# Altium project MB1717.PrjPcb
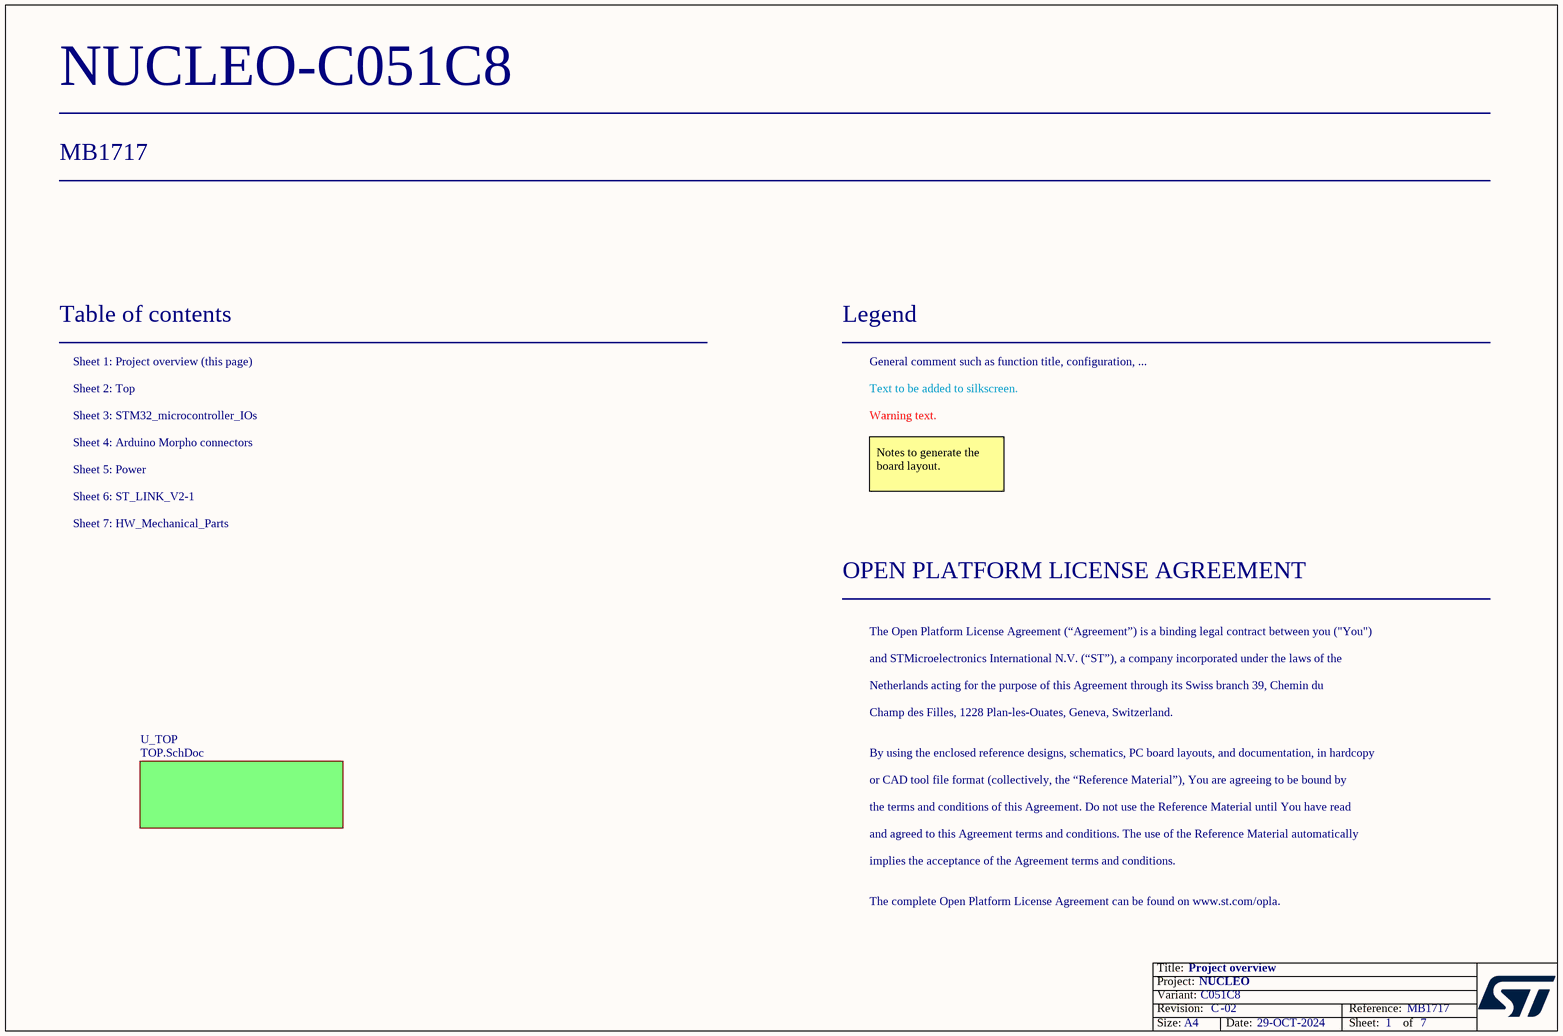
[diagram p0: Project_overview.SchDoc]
VariantName: C051C8; Board_Reference: MB1717; Board_PCB_Revision: C; Board_Name: NUCLEO; Board_Document_Date: 29-OCT-2024; Board_Assembly_Revision: 02
7 sheets, 148 parts. Net scope: flat (ports and power ports of the same name join across sheets).
Board file: MB1717.PcbDoc
Sheets:
  Project_overview.SchDoc
    U_TOP = TOP.SchDoc
      ST_LINK_V2-1 = ST_LINK_V2-1.SchDoc
      MCU = STM32_microcontroller_IOs.SchDoc
      Power = Power.SchDoc
      HW_Mechanical_Parts = HW_Mechanical_Parts.SchDoc
      U_Arduino_Morpho_connectors = Arduino_Morpho_connectors.SchDoc

## Sheet Project_overview.SchDoc: Project overview
size A4; Date: Not used; ApprovedBy: Not used; CheckedBy: Not used; Author: Not used; CompanyName: STMicroelectronics; DrawnBy: Not used; Engineer: Not used; Organization: Not used; Address1: Not used; Address2: Not used; Address3: Not used; Address4: Not used; DocumentNumber: 1; Revision: Not used; SheetNumber: 1; SheetTotal: 7

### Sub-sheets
U_TOP = TOP.SchDoc: no entries

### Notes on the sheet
- Table of contents
- Sheet 1: Project overview (this page)
- Legend
- General comment such as function title, configuration, ...
- Sheet 2: Top
- Sheet 4: Arduino Morpho connectors
- Sheet 3: STM32_microcontroller_IOs
- Text to be added to silkscreen.
- Warning text.
- Sheet 5: Power
- Sheet 6: ST_LINK_V2-1
- Notes to generate the board layout.
- Sheet 7: HW_Mechanical_Parts
- OPEN PLATFORM LICENSE AGREEMENT
- The Open Platform License Agreement (“Agreement”) is a binding legal contract between you ("You")
- and STMicroelectronics International N.V. (“ST”), a company incorporated under the laws of the
- Netherlands acting for the purpose of this Agreement through its Swiss branch 39, Chemin du
- Champ des Filles, 1228 Plan-les-Ouates, Geneva, Switzerland.
- By using the enclosed reference designs, schematics, PC board layouts, and documentation, in hardcopy
- or CAD tool file format (collectively, the “Reference Material”), You are agreeing to be bound by
- the terms and conditions of this Agreement. Do not use the Reference Material until You have read
- and agreed to this Agreement terms and conditions. The use of the Reference Material automatically
- implies the acceptance of the Agreement terms and conditions.
- The complete Open Platform License Agreement can be found on www.st.com/opla.

## Sheet TOP.SchDoc: TOP
size A4; CompanyName: STMicroelectronics; Organization: Microcontrollers Division; SheetNumber: 2; SheetTotal: 7
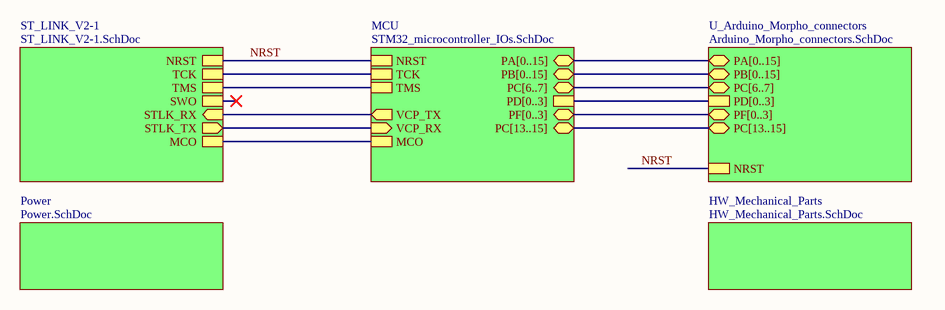
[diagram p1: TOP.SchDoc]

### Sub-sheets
HW_Mechanical_Parts = HW_Mechanical_Parts.SchDoc: no entries
MCU = STM32_microcontroller_IOs.SchDoc: NRST, MCO, PA[0..15] (bidir), PB[0..15] (bidir), TCK, TMS, PD[0..3], PC[6..7] (bidir), PC[13..15] (bidir), VCP_RX (in), VCP_TX (out), PF[0..3] (bidir)
Power = Power.SchDoc: no entries
ST_LINK_V2-1 = ST_LINK_V2-1.SchDoc: TMS, TCK, MCO, NRST, STLK_RX (in), STLK_TX (out), SWO
U_Arduino_Morpho_connectors = Arduino_Morpho_connectors.SchDoc: PA[0..15] (bidir), PB[0..15] (bidir), NRST, PD[0..3], PC[6..7] (bidir), PC[13..15] (bidir), PF[0..3] (bidir)

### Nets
NRST: sheet ST_LINK_V2-1/NRST, sheet MCU/NRST, sheet U_Arduino_Morpho_connectors/NRST
(unnamed): sheet ST_LINK_V2-1/TMS, sheet MCU/TMS
(unnamed): sheet ST_LINK_V2-1/TCK, sheet MCU/TCK  [a separate net that carries the same name]
(unnamed): sheet ST_LINK_V2-1/MCO, sheet MCU/MCO  [a separate net that carries the same name]
(unnamed): sheet ST_LINK_V2-1/STLK_RX, sheet MCU/VCP_TX  [a separate net that carries the same name]
(unnamed): sheet ST_LINK_V2-1/STLK_TX, sheet MCU/VCP_RX  [a separate net that carries the same name]

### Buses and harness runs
bus sheet MCU/PA[0..15] = sheet U_Arduino_Morpho_connectors/PA[0..15]
bus sheet MCU/PB[0..15] = sheet U_Arduino_Morpho_connectors/PB[0..15]
bus sheet MCU/PC[6..7] = sheet U_Arduino_Morpho_connectors/PC[6..7]
bus sheet MCU/PC[13..15] = sheet U_Arduino_Morpho_connectors/PC[13..15]
bus sheet MCU/PD[0..3] = sheet U_Arduino_Morpho_connectors/PD[0..3]
bus sheet MCU/PF[0..3] = sheet U_Arduino_Morpho_connectors/PF[0..3]

## Sheet ST_LINK_V2-1.SchDoc: ST_LINK_V2-1
size A4; CompanyName: STMicroelectronics; Organization: Microcontrollers Division; SheetNumber: 6; SheetTotal: 7
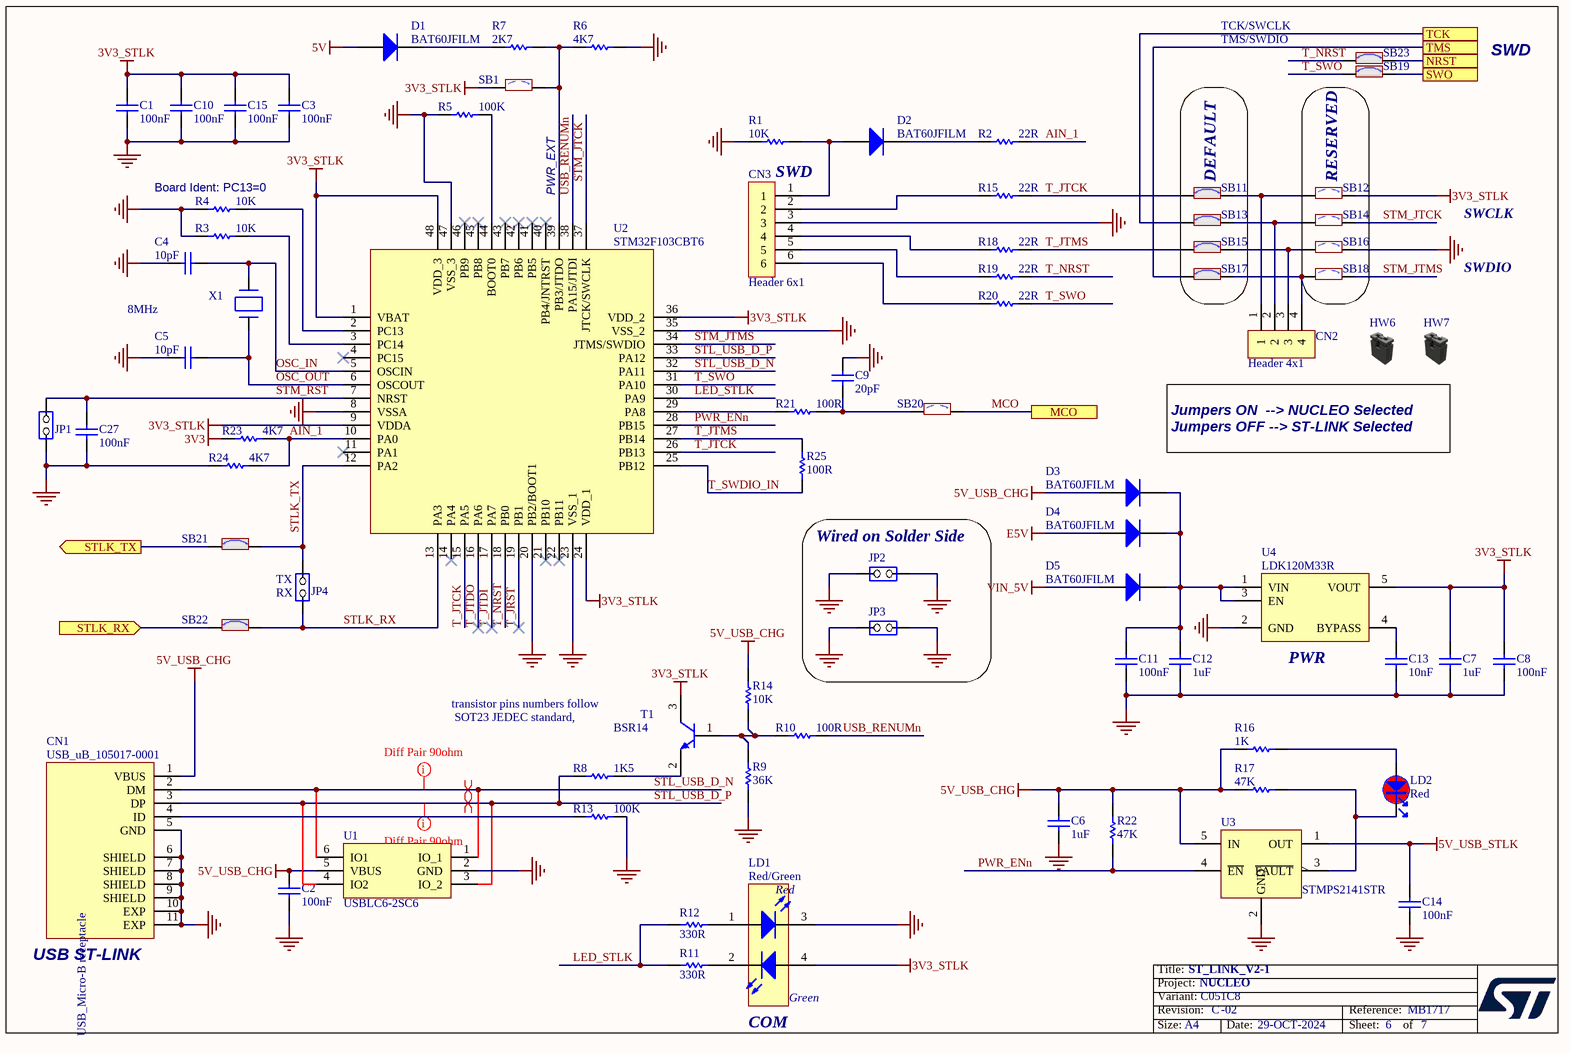
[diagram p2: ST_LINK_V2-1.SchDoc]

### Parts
C1  value 100nF  [C0603]  (hidden comment: Capacitor)
C2  value 100nF  [C0603]  (hidden comment: Capacitor)
C3  value 100nF  [C0603]  (hidden comment: Capacitor)
C4  value 10pF  [C0603]  (hidden comment: Capacitor)
C5  value 10pF  [C0603]  (hidden comment: Capacitor)
C6  value 1uF  [C0603]  (hidden comment: Capacitor)
C7  value 1uF  [C0603]  (hidden comment: Capacitor)
C8  value 100nF  [C0603]  (hidden comment: Capacitor)
C9  value 20pF  [C0603]  (hidden comment: Capacitor)
C10  value 100nF  [C0603]  (hidden comment: Capacitor)
C11  value 100nF  [C0603]  (hidden comment: Capacitor)
C12  value 1uF  [C0603]  (hidden comment: Capacitor)
C13  value 10nF  [C0603]  (hidden comment: Capacitor)
C14  value 100nF  [C0603]  (hidden comment: Capacitor)
C15  value 100nF  [C0603]  (hidden comment: Capacitor)
C27  value 100nF  [C0603]  (hidden comment: Capacitor)
CN1  value USB_uB_105017-0001  [CON_USBMICROB_MOLEX_105017-0001_H2P90]  (hidden comment: USB_uB_105017.0001)
CN2  Header 4x1  [CON_SAMTEC_TSW-104-07-G-S]
CN3  Header 6x1  [CON_SAMTEC_TSW-106-07-X-S]
D1  BAT60JFILM  [DIO_SOD323]
D2  BAT60JFILM  [DIO_SOD323]
D3  BAT60JFILM  [DIO_SOD323]
D4  BAT60JFILM  [DIO_SOD323]
D5  BAT60JFILM  [DIO_SOD323]
HW6  Shunt Black 2.54mm  (value not drawn)  (mechanical)
HW7  Shunt Black 2.54mm  (value not drawn)  (mechanical)
JP1  Jumper_Header 2x1  [CON_SAMTEC_TSW-102-07-G-S]  (value not drawn)
JP2  Jumper_Header 2x1  [CON_SAMTEC_TSW-102-09-X-S]  (value not drawn)
JP3  Jumper_Header 2x1  [CON_SAMTEC_TSW-102-09-X-S]  (value not drawn)
JP4  Jumper_Header 2x1  [CON_SAMTEC_TSW-102-07-G-S]  (value not drawn)
LD1  value Red/Green  [LED_BI-GR_WE-150141SV73110]  (hidden comment: LED_BICOLOR)
LD2  value Red  [LED_0603_OSRAM_LS-Q976-NR-1_RED_1A2K_H0P8]  (hidden comment: LED_red)
R1  value 10K  [R0603]  (hidden comment: Resistor)
R2  value 22R  [R0603]  (hidden comment: Resistor)
R3  value 10K  [R0603]  (hidden comment: Resistor)
R4  value 10K  [R0603]  (hidden comment: Resistor)
R5  value 100K  [R0603]  (hidden comment: Resistor)
R6  value 4K7  [R0603]  (hidden comment: Resistor)
R7  value 2K7  [R0603]  (hidden comment: Resistor)
R8  value 1K5  [R0603]  (hidden comment: Resistor)
R9  value 36K  [R0603]  (hidden comment: Resistor)
R10  value 100R  [R0603]  (hidden comment: Resistor)
R11  value 330R  [R0603]  (hidden comment: Resistor)
R12  value 330R  [R0603]  (hidden comment: Resistor)
R13  value 100K  [R0603]  (hidden comment: Resistor)
R14  value 10K  [R0603]  (hidden comment: Resistor)
R15  value 22R  [R0603]  (hidden comment: Resistor)
R16  value 1K  [R0603]  (hidden comment: Resistor)
R17  value 47K  [R0603]  (hidden comment: Resistor)
R18  value 22R  [R0603]  (hidden comment: Resistor)
R19  value 22R  [R0603]  (hidden comment: Resistor)
R20  value 22R  [R0603]  (hidden comment: Resistor)
R21  value 100R  [R0603]  (hidden comment: Resistor)
R22  value 47K  [R0603]  (hidden comment: Resistor)
R23  value 4K7  [R0603]  (hidden comment: Resistor)
R24  value 4K7  [R0603]  (hidden comment: Resistor)
R25  value 100R  [R0603]  (hidden comment: Resistor)
SB1  SB_OFF  [SOLDER-BRIDGE_R0603-0R]  (value not drawn)
SB11  SB_ON  [SOLDER-BRIDGE_R0603-0R]  (value not drawn)
SB12  SB_OFF  [SOLDER-BRIDGE_R0603-0R]  (value not drawn)
SB13  SB_ON  [SOLDER-BRIDGE_R0603-0R]  (value not drawn)
SB14  SB_OFF  [SOLDER-BRIDGE_R0603-0R]  (value not drawn)
SB15  SB_ON  [SOLDER-BRIDGE_R0603-0R]  (value not drawn)
SB16  SB_OFF  [SOLDER-BRIDGE_R0603-0R]  (value not drawn)
SB17  SB_ON  [SOLDER-BRIDGE_R0603-0R]  (value not drawn)
SB18  SB_OFF  [SOLDER-BRIDGE_R0603-0R]  (value not drawn)
SB19  SB_ON  [SOLDER-BRIDGE_R0603-0R]  (value not drawn)
SB20  SB_OFF  [SOLDER-BRIDGE_R0603-0R]  (value not drawn)
SB21  SB_ON  [SOLDER-BRIDGE_R0603-0R]  (value not drawn)
SB22  SB_ON  [SOLDER-BRIDGE_R0603-0R]  (value not drawn)
SB23  SB_ON  [SOLDER-BRIDGE_R0603-0R]  (value not drawn)
T1  value BSR14  [NPN_SOT23]  (hidden comment: 9013-SOT23)
U1  USBLC6-2SC6  [ESD_SOT23-6L]
U2  STM32F103CBT6  [ICC_LQFP48_7X7_P050]
U3  STMPS2141STR  [MOS_SOT23-5L]
U4  LDK120M33R  [REG_SOT23-5L]
X1  value 8MHz  [CRY_NX3225GD_2P]  (hidden comment: XTAL_2_PINS)

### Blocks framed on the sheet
DEFAULT: SB11 SB13 SB15 SB17
RESERVED: SB12 SB14 SB16 SB18
Wired on Solder Side: JP2 JP3

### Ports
MCO, NRST, STLK_RX (in), STLK_TX (out), SWO, TCK, TMS

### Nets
3V3: R23.1
3V3_STLK: C1.2 C3.2 C7.2 C8.2 C10.2 C15.2 LD1.4(Green_anode) SB1.1 SB12.2 T1.3(C) U2.1(VBAT) U2.9(VDDA) U2.24(VDD_1) U2.36(VDD_2) U2.48(VDD_3) U4.5(VOUT)
5V: D1.1(A)
5V_USB_CHG: C2.2 C6.2 CN1.1(VBUS) D3.1(A) R14.2 R16.2 R17.2 R22.2 U1.5(VBUS) U3.5(IN)
5V_USB_STLK: C14.2 U3.1(OUT)
E5V: D4.1(A)
GND: C1.1 C2.1 C3.1 C4.1 C5.1 C6.1 C7.1 C8.1 C9.2 C10.1 C11.1 C12.1 C13.1 C14.1 C15.1 C27.2 CN1.5(GND) CN1.6(SHIELD) CN1.7(SHIELD) CN1.8(SHIELD) CN1.9(SHIELD) CN1.10(EXP) CN1.11(EXP) CN3.3 JP1.2(NO) JP2.1(COMMON) JP2.2(NO) JP3.1(COMMON) JP3.2(NO) LD1.3(RED_cathode) R1.2 R3.1 R4.1 R5.1 R6.2 R9.1 R13.2 R24.1 SB16.2 U1.2(GND) U2.8(VSSA) U2.20(PB2/BOOT1) U2.23(VSS_1) U2.35(VSS_2) U2.47(VSS_3) U3.2(GND) U4.2(GND)
VIN_5V: D5.1(A)
AIN_1: R2.2 R23.2 R24.2 U2.10(PA0)
LED_STLK: R11.1 R12.1 U2.30(PA9)
MCO: SB20.2 ; port MCO
NRST: SB23.2 ; port NRST
OSC_IN: C4.2 U2.5(OSCIN) X1.2(X2)
OSC_OUT: C5.2 U2.6(OSCOUT) X1.1(X1)
PA13: SB17.1 ; port TMS
PA14: SB13.1 ; port TCK
PWR_ENn: R22.1 U2.28(PB15) U3.4(~{EN})
STL_USB_D_N: CN1.2(DM) U1.1(IO_1) U1.6(IO1) U2.32(PA11)
STL_USB_D_P: CN1.3(DP) R8.1 U1.3(IO_2) U1.4(IO2) U2.33(PA12)
STLK_RX: JP4.1(COMMON) SB22.2 U2.13(PA3)
STLK_TX: JP4.2(NO) SB21.2 U2.12(PA2)
STM_JTCK: SB14.2 U2.37(JTCK/SWCLK)
STM_JTMS: SB18.2 U2.34(JTMS/SWDIO)
STM_RST: C27.1 JP1.1(COMMON) U2.7(NRST)
T_JRST: U2.19(PB1)
T_JTCK: R15.2 SB11.1 U2.15(PA5) U2.26(PB13)
T_JTDI: U2.17(PA7)
T_JTDO: U2.16(PA6)
T_JTMS: R18.2 R25.2 SB15.1 U2.27(PB14)
T_NRST: R19.2 SB23.1 U2.18(PB0)
T_SWDIO_IN: R25.1 U2.25(PB12)
T_SWO: R20.2 SB19.1 U2.31(PA10)
USB_RENUMn: R10.2 U2.38(PA15/JTDI)
NetC9_1: C9.1 R21.2 SB20.1
NetC11_2: C11.2 C12.2 D3.2(K) D4.2(K) D5.2(K) U4.1(VIN) U4.3(EN)
NetC13_2: C13.2 U4.4(BYPASS)
NetCN1_4: CN1.4(ID) R13.1
NetCN2_1: CN2.1 SB11.2 SB12.1
NetCN2_2: CN2.2 SB13.2 SB14.1
NetCN2_3: CN2.3 SB15.2 SB16.1
NetCN2_4: CN2.4 SB17.2 SB18.1
NetCN3_1: CN3.1 D2.1(A) R1.1
NetCN3_2: CN3.2 R15.1
NetCN3_4: CN3.4 R18.1
NetCN3_5: CN3.5 R19.1
NetCN3_6: CN3.6 R20.1
NetD1_2: D1.2(K) R7.1
NetD2_2: D2.2(K) R2.1
NetLD1_1: LD1.1(Red_anode) R12.2
NetLD1_2: LD1.2(Green_cathode) R11.2
NetLD2_1: LD2.1 R16.1
NetLD2_2: LD2.2 R17.1 U3.3(~{FAULT})
NetR3_2: R3.2 U2.3(PC14)
NetR4_2: R4.2 U2.2(PC13)
NetR5_2: R5.2 U2.44(BOOT0)
NetR6_1: R6.1 R7.2 SB1.2 U2.39(PB3/JTDO)
NetR8_2: R8.2 T1.2(E)
NetR9_2: R9.2 R10.1 R14.1 T1.1(B)
NetR21_1: R21.1 U2.29(PA8)
NetSB19_2: SB19.2 ; port SWO
NetSB21_1: SB21.1 ; port STLK_TX
NetSB22_1: SB22.1 ; port STLK_RX

Not connected (* = marked no-connect by the designer): U2 4(PC15)* 11(PA1)* 14(PA4)* 21(PB10)* 22(PB11)* 40(PB4/JNTRST)* 41(PB5)* 42(PB6)* 43(PB7)* 45(PB8)* 46(PB9)*

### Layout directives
mark named Diff Pair 90ohm: STL_USB_D_N, STL_USB_D_P
differential pair: STL_USB_D_N, STL_USB_D_P

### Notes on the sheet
- TCK/SWCLK
- TMS/SWDIO
- SWD
- (near R4) Board Ident: PC13=0
- PWR_EXT
- SWCLK
- SWDIO
- Jumpers ON  --> NUCLEO Selected
  Jumpers OFF --> ST-LINK Selected
- (near JP4) TX
- (near JP4) RX
- (near U4) PWR
- (near T1) transistor pins numbers follow
  SOT23 JEDEC standard,
- (near CN1) USB ST-LINK
- COM

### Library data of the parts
C1-C3 C8 C10 C11 C14 C15 C27 = MCD-00211: Capacitor, MLCC, 100nF, 16V, X7R, +/-10%, 0603, T=0.8mm; Manufacturer_Part_Number: CC0603KRX7R7BB104; Manufacturer: YAGEO; Part_Preference: Recommended; Partial_Alternate_Internal_Part_Number: MCD-01099; Order_Code_RS: 669-8763; Component_Country_Of_Origin: China; ShowFields: YES; ID: 2659
C4 C5 = MCD-00637: Capacitor, MLCC, 10pF, 50V, NPO, +/-5%, 0603, T=0.8mm; Manufacturer_Part_Number: CC0603JRNPO9BN100; Manufacturer: YAGEO; Part_Preference: Recommended; Order_Code_RS: 616-9054; Component_Country_Of_Origin: China; ShowFields: YES; ID: 3104
C6 C7 C12 = MCD-00010: Capacitor, MLCC, 1uF, 16V, X5R, +/-10%, 0603, T=0.8mm; Manufacturer_Part_Number: CC0603KRX5R7BB105; Manufacturer: YAGEO; Part_Preference: Recommended; Order_Code_RS: 2370680; Component_Country_Of_Origin: China; ShowFields: YES; ID: 2470
C9 = MCD-00638: Capacitor, MLCC, 20pF, 50V, NPO, +/-5%, 0603, T=0.8mm; Manufacturer_Part_Number: CC0603JRNPO9BN200; Manufacturer: YAGEO; Part_Preference: Recommended; Component_Country_Of_Origin: China; ShowFields: YES; ID: 3109
C13 = MCD-00017: Capacitor, MLCC, 10nF, 50V, X7R, +/-10%, 0603, T=0.8mm; Manufacturer_Part_Number: CC0603KRX7R9BB103; Manufacturer: YAGEO; Part_Preference: Recommended; Order_Code_RS: 722236; Component_Country_Of_Origin: China; ShowFields: YES; ID: 2500
CN1 = MCD-00028: MicroUSB_TypeB, 5pins, 0.65mm, RA, SMD, T=2.9mm; Part_Type: Connector; Manufacturer_Part_Number: 1050170001; Manufacturer: MOLEX; Part_Preference: Recommended; Order_Code_RS: 2293836; Component_Country_Of_Origin: Unknown; ShowFields: YES; ID: 2489
CN2 = MCD-00029: Header, 4x1, 2.54mm, VR, TH, T=5.84mm/2.54mm; Part_Type: Connector; Manufacturer_Part_Number: TSW-104-07-G-S; Manufacturer: SAMTEC; Part_Preference: Recommended; Order_Code_RS: 161-2460; Component_Country_Of_Origin: China, Costa Rica, Malaysia, USA, Vietnam; ShowFields: YES; ID: 2487
CN3 = MCD-00212: Header, 6x1, 2.54mm, VR, TH, T=5.84mm/2.54mm; Part_Type: Connector; Manufacturer_Part_Number: TSW-106-07-G-S; Manufacturer: SAMTEC; Part_Preference: Recommended; Order_Code_RS: 161-2505; Component_Country_Of_Origin: China, Costa Rica, Malaysia, USA, Vietnam; ShowFields: YES; ID: 2657
D1-D5 = MCD-00034: Diode, Schottky, 0V53, 1A, 10V, SOD323; Manufacturer: STMICROELECTRONICS; BMS_Part_Number: 9151097; Part_Preference: Recommended; Manufacturer_HQ_COO: EU; Order_Code_RS: 714-6879; Component_Country_Of_Origin: China; ShowFields: YES; ID: 2483
HW6 HW7 = MCD-00043: Jumper, 2.54mm, Black, 4.3A, 6.1mm, 5mR; Manufacturer_Part_Number: SNT-100-BK-G; Manufacturer: SAMTEC; Part_Type: Misc; Part_Preference: Recommended; Manufacturer_HQ_COO: Unknown; Full_Alternate_Internal_Part_Number: MCD-02388; Partial_Alternate_Internal_Part_Number: MCD-01849, MCD-01864; Value: SNT-100-BK-G; Order_Code_RS: 158-7784; Component_Country_Of_Origin: China, Costa Rica, Malaysia, USA, Vietnam; Alternate_EMS: A; ShowFields: YES; ID: 2551
JP1 JP4 = MCD-00045: Header, 2x1, 2.54mm, VR, TH, T=5.84mm/2.54mm; Part_Type: Connector; Manufacturer_Part_Number: TSW-102-07-G-S; Manufacturer: SAMTEC; Part_Preference: Recommended; Full_Alternate_Internal_Part_Number: MCD-02390; Partial_Alternate_Internal_Part_Number: MCD-02957, MCD-03720, MCD-04249; Order_Code_RS: 2505044; Component_Country_Of_Origin: China, Costa Rica, Malaysia, USA, Vietnam; ShowFields: YES; ID: 2545
JP2 JP3 = MCD-00214: Header, 2x1, 2.54mm, VR, TH, T=5.84mm/10.16mm; Part_Type: Connector; Manufacturer_Part_Number: TSW-102-09-G-S; Manufacturer: SAMTEC; Part_Preference: Recommended; Full_Alternate_Internal_Part_Number: MCD-02393; Partial_Alternate_Internal_Part_Number: MCD-03591, MCD-03719, MCD-04227; Order_Code_RS: 180-3129; Component_Country_Of_Origin: China, Costa Rica, Malaysia, USA, Vietnam; ShowFields: YES; ID: 2652
LD1 = MCD-02631: LED Bicolor, Red/Green, 2V, 20mA, 4-PLCC; Part_Type: Display; Manufacturer_Part_Number: 150141SV73110; Manufacturer: WURTH ELEKTRONIK; Part_Preference: Recommended; Partial_Alternate_Internal_Part_Number: MCD-02402; Order_Code_RS: 184-6963; ShowFields: YES; ID: 4737; Component_Country_Of_Origin: China
LD2 = MCD-00586: LED, Red, 2V, 20mA, 0603; Manufacturer_Part_Number: LS Q976-NR-1; Manufacturer: OSRAM OPTO SEMICONDUCTORS; Part_Type: Display; Part_Preference: Recommended; Partial_Alternate_Internal_Part_Number: MCD-02787; Order_Code_RS: 121-7784; Component_Country_Of_Origin: Unknown; ShowFields: YES; ID: 3158
R1 R3 R4 R14 = MCD-00220: Resistor, 10K, 0603, +/-1%, 1/10W; Manufacturer_Part_Number: RC0603FR-0710KL; Manufacturer: YAGEO; Part_Preference: Recommended; Component_Country_Of_Origin: China; ShowFields: YES; ID: 2649
R2 R15 R18-R20 = MCD-00066: Resistor, 22R, 0603, +/-1%, 1/10W; Manufacturer_Part_Number: RC0603FR-0722RL; Manufacturer: YAGEO; Part_Preference: Recommended; Order_Code_RS: 9238280; Component_Country_Of_Origin: China; ShowFields: YES; ID: 2530
R5 R13 = MCD-00223: Resistor, 100K, 0603, +/- 1%, 1/10W; Manufacturer_Part_Number: RC0603FR-07100KL; Manufacturer: YAGEO; Part_Preference: Recommended; Component_Country_Of_Origin: China; ShowFields: YES; ID: 2647
R6 R23 R24 = MCD-00219: Resistor, 4K7, 0603, +/-1%, 1/10W; Manufacturer_Part_Number: RC0603FR-074K7L; Manufacturer: YAGEO; Part_Preference: Recommended; Component_Country_Of_Origin: China; ShowFields: YES; ID: 2648
R7 = MCD-00218: Resistor, 2K7 ,0603, +/-1%, 1/10W; Manufacturer_Part_Number: RC0603FR-072K7L; Manufacturer: YAGEO; BMS_Part_Number: 9129767; Part_Preference: Recommended; Component_Country_Of_Origin: China; ShowFields: YES; ID: 2650
R8 = MCD-00217: Resistor, 1K5, 0603, +/-1%, 1/10W; Manufacturer_Part_Number: RC0603FR-071K5L; Manufacturer: YAGEO; BMS_Part_Number: 9129766; Part_Preference: Recommended; Component_Country_Of_Origin: China; ShowFields: YES; ID: 2651
R9 = MCD-00221: Resistor, 36K, 0603, +/-1%, 1/10W; Manufacturer_Part_Number: RC0603FR-0736KL; Manufacturer: YAGEO; Part_Preference: Recommended; Component_Country_Of_Origin: China; ShowFields: YES; ID: 2646
R10 R21 R25 = MCD-00224: Resistor, 100R, 0603, +/-1%, 1/10W; Manufacturer_Part_Number: RC0603FR-07100RL; Manufacturer: YAGEO; Part_Preference: Recommended; Component_Country_Of_Origin: China; ShowFields: YES; ID: 2643
R11 R12 = MCD-00197: Resistor, 330R, 0603, +/-1%, 1/10W; Manufacturer_Part_Number: RC0603FR-07330RL; Manufacturer: YAGEO; BMS_Part_Number: 9129729; Part_Preference: Recommended; Component_Country_Of_Origin: China; ShowFields: YES; ID: 2672
R16 = MCD-00070: Resistor, 1K, 0603, +/-1%, 1/10W; Manufacturer_Part_Number: RC0603FR-071KL; Manufacturer: YAGEO; Part_Preference: Recommended; Order_Code_RS: 9238484RL; Component_Country_Of_Origin: China; ShowFields: YES; ID: 2522
R17 R22 = MCD-00222: Resistor, 47K, 0603, 1%, 1/10W; Manufacturer_Part_Number: RC0603FR-0747KL; Manufacturer: YAGEO; Part_Preference: Recommended; Component_Country_Of_Origin: China; ShowFields: YES; ID: 2645
SB1 SB12 SB14 SB16 SB18 SB20 = MCD-00072: Resistor, 0R, SB0603, 5%, 0.1W; Manufacturer_Part_Number: RC0603JR-070RL; Manufacturer: YAGEO; Part_Preference: Recommended; Manufacturer_HQ_COO: Unknown; Order_Code_RS: 199-5647; Component_Country_Of_Origin: China; ShowFields: YES; ID: 2520
SB11 SB13 SB15 SB17 SB19 SB21-SB23 = MCD-00071: Resistor, 0R, SB0603, 5%, 0.1W; Manufacturer_Part_Number: RC0603JR-070RL; Manufacturer: YAGEO; Part_Preference: Recommended; Manufacturer_HQ_COO: Unknown; Order_Code_RS: 199-5647; Component_Country_Of_Origin: China; ShowFields: YES; ID: 2521
T1 = MCD-00073: Transistor, NPN, 40V, 800mA, SOT23; Manufacturer: ON SEMICONDUCTOR; Part_Preference: Recommended; Partial_Alternate_Internal_Part_Number: MCD-01737, MCD-03305, , MCD-02988; Component_Country_Of_Origin: Unknown; ShowFields: YES; ID: 2519
U1 = MCD-00163: Diode, ESD protection, 5V25, 150nA, 6V, SOT23-6; Manufacturer: STMICROELECTRONICS; BMS_Part_Number: 9151075; Part_Preference: Recommended; Order_Code_RS: 920-6266; Component_Country_Of_Origin: China; ShowFields: YES; ID: 2707
U2 = MCD-00085: MCU, ARM Cortex-M3 32-bit, 64 or 128KB Flash, 20KB RAM, No Crypto; Manufacturer: STMICROELECTRONICS; Part_Type: IC; BMS_Part_Number: 9175111; Part_Preference: Recommended; Manufacturer_HQ_COO: EU; Order_Code_RS: 402-273; Component_Country_Of_Origin: Malaysia; ShowFields: YES; ID: 2507
U3 = MCD-00083: Power Switch, Enhanced single channel; Part_Type: IC; Manufacturer: STMICROELECTRONICS; BMS_Part_Number: 9159003; Part_Preference: Recommended; Manufacturer_HQ_COO: EU; Order_Code_RS: 880-5406; Component_Country_Of_Origin: Malaysia; ShowFields: YES; ID: 2509
U4 = MCD-00663: LDO, 3V3, 200mA, Low quiescent current, Very low noise; Part_Type: IC; Manufacturer: STMICROELECTRONICS; BMS_Part_Number: 9176330; Part_Preference: Recommended; Manufacturer_HQ_COO: EU; Partial_Alternate_Internal_Part_Number: MCD-03279; Order_Code_RS: 188-9202; Component_Country_Of_Origin: China; ShowFields: YES; ID: 3082
X1 = MCD-00092: Crystal, 8MHz, 8pF, +/-20ppm, 500R, 3.2x2.5mm; Part_Type: Crystal_Osc; Manufacturer_Part_Number: NX3225GD-8MHZ-EXS00A-CG04874; Manufacturer: NDK; BMS_Part_Number: 9157029; Part_Preference: Recommended; Component_Country_Of_Origin: Unknown; ShowFields: YES; ID: 2776

## Sheet STM32_microcontroller_IOs.SchDoc: STM32_microcontroller_IOs
size A4; CompanyName: STMicroelectronics; Organization: Microcontrollers Division; SheetNumber: 3; SheetTotal: 7
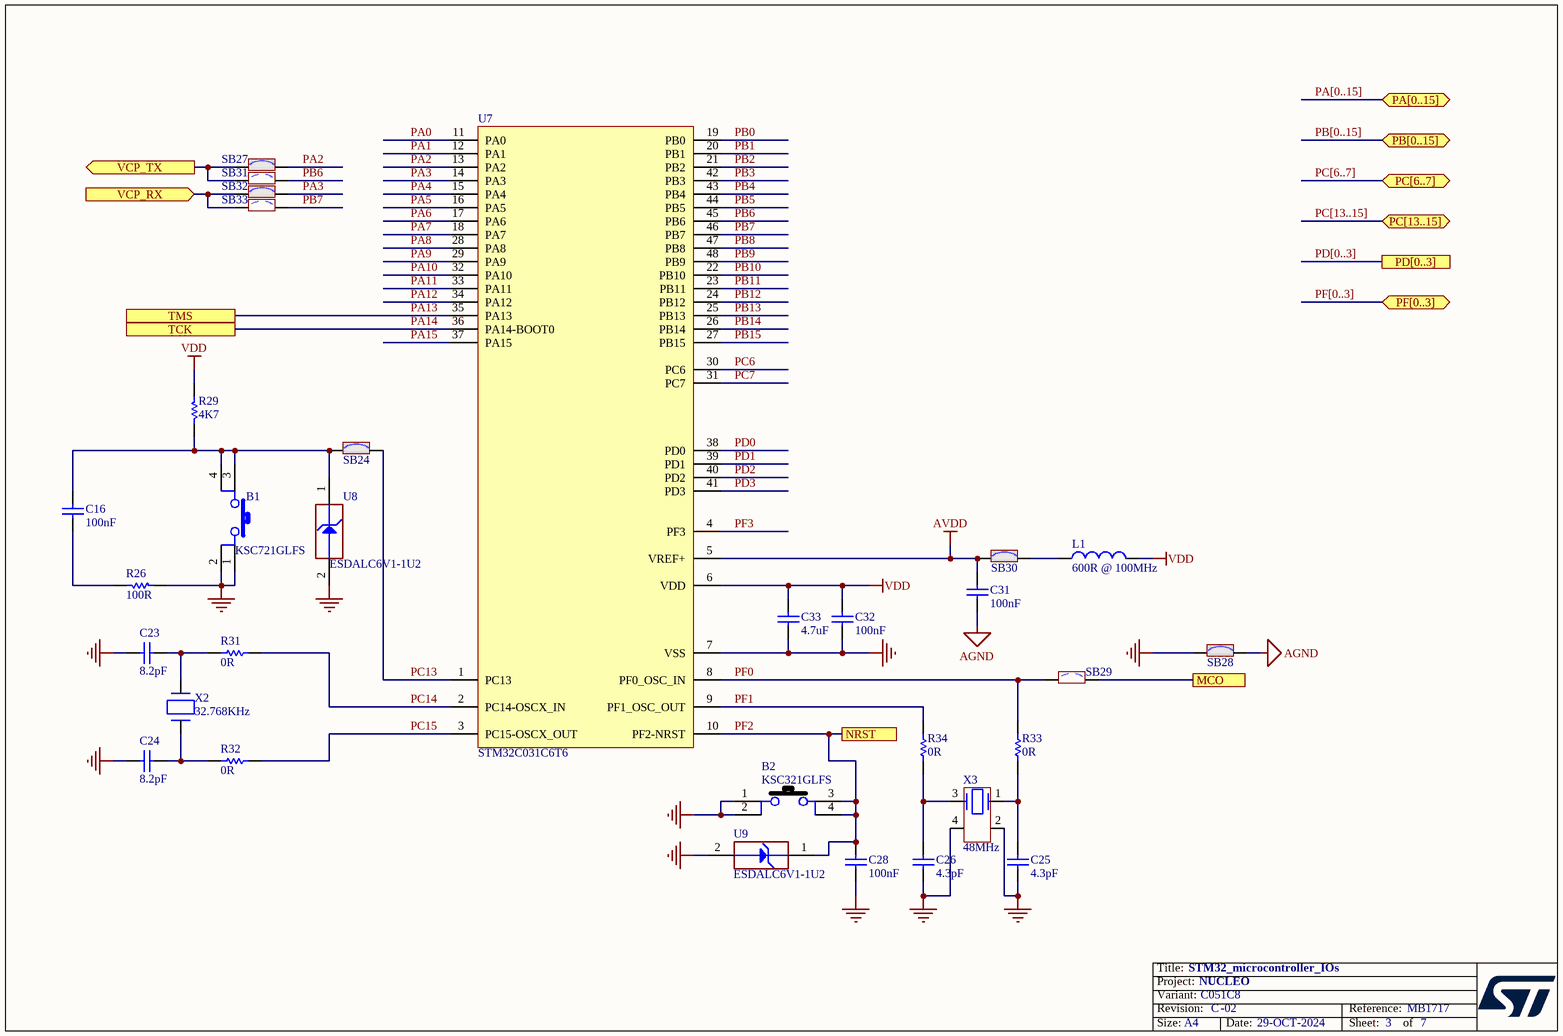
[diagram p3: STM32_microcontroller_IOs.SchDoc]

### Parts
B1  value KSC721GLFS  [SWI_C&K_KSC721GLFS_BLUE]  (hidden comment: SW_BLUE_KSC721GLFS)
B2  value KSC321GLFS  [SWI_C&K_KSC321GLFS_BLACK]  (hidden comment: SW_BLACK_KSC321GLFS)
C16  value 100nF  [C0603]  (hidden comment: Capacitor)
C23  value 8.2pF  [C0402]  (hidden comment: Capacitor)
C24  value 8.2pF  [C0402]  (hidden comment: Capacitor)
C25  value 4.3pF  [C0402]  (hidden comment: Capacitor)
C26  value 4.3pF  [C0402]  (hidden comment: Capacitor)
C28  value 100nF  [C0603]  (hidden comment: Capacitor)
C31  value 100nF  [C0603]  (hidden comment: Capacitor)
C32  value 100nF  [C0603]  (hidden comment: Capacitor)
C33  value 4.7uF  [C0603]  (hidden comment: Capacitor)
L1  value 600R @ 100MHz  [L0603]  (hidden comment: BEAD)
R26  value 100R  [R0603]  (hidden comment: Resistor)
R29  value 4K7  [R0603]  (hidden comment: Resistor)
R31  value 0R  [R0402]  (hidden comment: Resistor)
R32  value 0R  [R0402]  (hidden comment: Resistor)
R33  value 0R  [R0402]  (hidden comment: Resistor)
R34  value 0R  [R0402]  (hidden comment: Resistor)
SB24  SB_ON  [SOLDER-BRIDGE_R0603-0R]  (value not drawn)
SB27  SB_ON  [SOLDER-BRIDGE_R0603-0R]  (value not drawn)
SB28  SB_ON  [SOLDER-BRIDGE_R0603-0R]  (value not drawn)
SB29  SB_OFF  [SOLDER-BRIDGE_R0603-0R]  (value not drawn)
SB30  SB_ON  [SOLDER-BRIDGE_R0603-0R]  (value not drawn)
SB31  SB_OFF  [SOLDER-BRIDGE_R0603-0R]  (value not drawn)
SB32  SB_ON  [SOLDER-BRIDGE_R0603-0R]  (value not drawn)
SB33  SB_OFF  [SOLDER-BRIDGE_R0603-0R]  (value not drawn)
U7  STM32C031C6T6  [ICC_LQFP48_7X7_P050]
U8  value ESDALC6V1-1U2  [ESD_ST0201]  (hidden comment: ESD-TRANSIL)
U9  value ESDALC6V1-1U2  [ESD_ST0201]  (hidden comment: ESD-TRANSIL)
X2  value 32.768KHz  [CRY_NX2012SA_2P]  (hidden comment: XTAL_2_PINS)
X3  value 48MHz  [CRY_NX1612SA_4P]  (hidden comment: XTAL_4_PINS)

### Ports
MCO, NRST, PA[0..15] (bidir), PB[0..15] (bidir), PC[6..7] (bidir), PC[13..15] (bidir), PD[0..3], PF[0..3] (bidir), TCK, TMS, VCP_RX (in), VCP_TX (out)

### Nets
AGND: C31.1 SB28.2
AVDD: C31.2 SB30.1 U7.5(VREF+)
GND: B1.1 B1.2 B2.1 B2.2 C23.1 C24.1 C25.1 C26.1 C28.1 C32.1 C33.1 R26.1 SB28.1 U7.7(VSS) U8.2(GND) U9.2(GND) X3.2 X3.4
VDD: C32.2 C33.2 L1.2 R29.2 U7.6(VDD)
MCO: SB29.2 ; port MCO
PA0: U7.11(PA0)
PA1: U7.12(PA1)
PA2: SB27.2 U7.13(PA2)
PA3: SB32.2 U7.14(PA3)
PA4: U7.15(PA4)
PA5: U7.16(PA5)
PA6: U7.17(PA6)
PA7: U7.18(PA7)
PA8: U7.28(PA8)
PA9: U7.29(PA9)
PA10: U7.32(PA10)
PA11: U7.33(PA11)
PA12: U7.34(PA12)
PA13: U7.35(PA13) ; port TMS
PA14: U7.36(PA14-BOOT0) ; port TCK
PA15: U7.37(PA15)
PB0: U7.19(PB0)
PB1: U7.20(PB1)
PB2: U7.21(PB2)
PB3: U7.42(PB3)
PB4: U7.43(PB4)
PB5: U7.44(PB5)
PB6: SB31.2 U7.45(PB6)
PB7: SB33.2 U7.46(PB7)
PB8: U7.47(PB8)
PB9: U7.48(PB9)
PB10: U7.22(PB10)
PB11: U7.23(PB11)
PB12: U7.24(PB12)
PB13: U7.25(PB13)
PB14: U7.26(PB14)
PB15: U7.27(PB15)
PC6: U7.30(PC6)
PC7: U7.31(PC7)
PC13: SB24.1 U7.1(PC13)
PC14: R31.2 U7.2(PC14-OSCX_IN)
PC15: R32.2 U7.3(PC15-OSCX_OUT)
PD0: U7.38(PD0)
PD1: U7.39(PD1)
PD2: U7.40(PD2)
PD3: U7.41(PD3)
PF0: R33.2 SB29.1 U7.8(PF0_OSC_IN)
PF1: R34.2 U7.9(PF1_OSC_OUT)
PF2: B2.3 B2.4 C28.2 U7.10(PF2-NRST) U9.1(IO1) ; port NRST  [project net NRST]
PF3: U7.4(PF3)
NetB1_3: B1.3 B1.4 C16.2 R29.1 SB24.2 U8.1(IO1)
NetC16_1: C16.1 R26.2
NetC23_2: C23.2 R31.1 X2.2(X2)
NetC24_2: C24.2 R32.1 X2.1(X1)
NetC25_2: C25.2 R33.1 X3.1
NetC26_2: C26.2 R34.1 X3.3
NetL1_1: L1.1 SB30.2
NetSB27_1: SB27.1 SB31.1 ; port VCP_TX
NetSB32_1: SB32.1 SB33.1 ; port VCP_RX

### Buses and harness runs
bus PA[0..15] = port PA[0..15]
bus PB[0..15] = port PB[0..15]
bus PC[6..7] = port PC[6..7]
bus PC[13..15] = port PC[13..15]
bus PD[0..3] = port PD[0..3]
bus PF[0..3] = port PF[0..3]

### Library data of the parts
B1 = MCD-00176: Switch tactile, SPST-NO, 32V, 50mA, 6.2x10mm; Part_Type: Misc; Manufacturer: C&K; Part_Preference: Recommended; Order_Code_RS: 894-9152; Component_Country_Of_Origin: France; ShowFields: YES; ID: 2693
B2 = MCD-00175: Switch tactile, SPST-NO, 32V, 50mA, 6.2x10mm; Part_Type: Misc; Manufacturer: C&K; Part_Preference: Recommended; Order_Code_RS: 894-9095; Component_Country_Of_Origin: France; ShowFields: YES; ID: 2692
C16 C28 C31 C32 = MCD-00211: as C1 on sheet ST_LINK_V2-1
C23 C24 = MCD-01932: Capacitor, MLCC, 8.2pF, 50V, NPO, +/-0.25pF, 0402, T=0.5mm; Manufacturer_Part_Number: CC0402CRNPO9BN8R2; Manufacturer: YAGEO; Part_Preference: Recommended; Component_Country_Of_Origin: China; ShowFields: YES; ID: 4032
C25 C26 = MCD-01706: Capacitor, MLCC, 4.3pF, 50V, NP0, +/-0.25pF, 0402, T=0.5mm; Manufacturer_Part_Number: CC0402CRNPO9BN4R3; Manufacturer: YAGEO; Part_Preference: Recommended; Component_Country_Of_Origin: China; ShowFields: YES; ID: 3806
C33 = MCD-00009: Capacitor, MLCC, 4.7uF, 16V, X5R, +/-10%, 0603, T=0.8mm; Manufacturer_Part_Number: CC0603KRX5R7BB475; Manufacturer: YAGEO; Part_Preference: Recommended; Partial_Alternate_Internal_Part_Number: MCD-03565; Component_Country_Of_Origin: China; Alternate_EMS: A; ShowFields: YES; ID: 2471
L1 = MCD-00047: Ferrite bead, 600R @1 00MHz, +/-25%, 350mA, 0R5, 0603, T=0.8mm; Manufacturer_Part_Number: FCM1608KF-601T03; Manufacturer: TAI-TECH; Part_Type: Inductor; Part_Preference: Recommended; Partial_Alternate_Internal_Part_Number: MCD-02959; Component_Country_Of_Origin: Unknown; ShowFields: YES; ID: 2546
R26 = MCD-00224: as R10 on sheet ST_LINK_V2-1
R29 = MCD-00219: as R6 on sheet ST_LINK_V2-1
R31-R34 = MCD-00052: Resistor, 0R, 0402, +/-5%, 1/16W; Manufacturer_Part_Number: RC0402JR-070RL; Manufacturer: YAGEO; Part_Preference: Recommended; Order_Code_RS: 9232516RL; Component_Country_Of_Origin: China; ShowFields: YES; ID: 2540
SB24 SB27 SB28 SB30 SB32 = MCD-00071: as SB11 on sheet ST_LINK_V2-1
SB29 SB31 SB33 = MCD-00072: as SB1 on sheet ST_LINK_V2-1
U7 = MCD-02301: MCU, ARM Cortex-M0+ 32-bit, 32KB Flash, 12KB RAM, No Crypto; Part_Type: IC; Part_Preference: Recommended; Manufacturer: STMICROELECTRONICS; ShowFields: YES; ID: 4407; Component_Country_Of_Origin: China
U8 U9 = MCD-00170: Diode, ESD TVS, 3V, 100nA, 8V, ST0201; Manufacturer: STMICROELECTRONICS; BMS_Part_Number: 9151132; Part_Preference: Recommended; Manufacturer_HQ_COO: EU; Component_Country_Of_Origin: China; ShowFields: YES; ID: 2696; Order_Code_RS: 795-8404
X2 = MCD-01479: Crystal, 32.768kHz, 6pF, +/-20ppm, 80K, 2.05x1.2mm; Part_Type: Crystal_Osc; Manufacturer_Part_Number: NX2012SA-32.768KHZ-EXS00A-MU00527; Manufacturer: NDK; BMS_Part_Number: 9157049; Part_Preference: Recommended; Component_Country_Of_Origin: Unknown; ShowFields: YES; ID: 3579
X3 = MCD-02262: Crystal, 48MHz, 7pF, +/-20 ppm, 80R, 1.6x1.2mm; Part_Type: Crystal_Osc; Manufacturer_Part_Number: NX1612SA-48MHZ-EXS00A-CS13734; Manufacturer: NDK; Part_Preference: Recommended; Component_Country_Of_Origin: Unknown; ShowFields: YES; ID: 4362

## Sheet Power.SchDoc: Power
size A4; CompanyName: STMicroelectronics; Organization: Microcontrollers Division; SheetNumber: 5; SheetTotal: 7
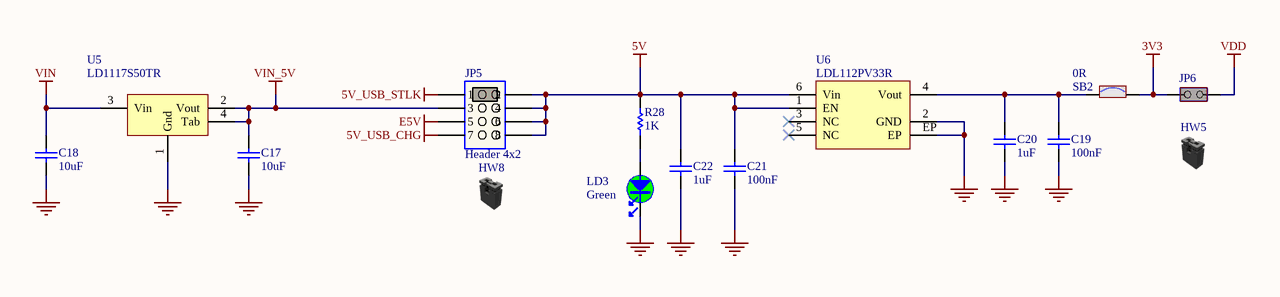
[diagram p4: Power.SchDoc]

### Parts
C17  value 10uF  [C0805]  (hidden comment: Capacitor)
C18  value 10uF  [C0805]  (hidden comment: Capacitor)
C19  value 100nF  [C0603]  (hidden comment: Capacitor)
C20  value 1uF  [C0603]  (hidden comment: Capacitor)
C21  value 100nF  [C0603]  (hidden comment: Capacitor)
C22  value 1uF  [C0603]  (hidden comment: Capacitor)
HW5  Shunt Black 2.54mm  (value not drawn)  (mechanical)
HW8  Shunt Black 2.54mm  (value not drawn)  (mechanical)
JP5  value Header 4x2  [CON_SAMTEC_TSW-104-07-X-D]  (hidden comment: Jumper_Header 4x2 Fitted 1-2)
JP6  Jumper_Header 2x1 Fitted  [CON_SAMTEC_TSW-102-07-G-S]  (value not drawn)
LD3  value Green  [LED_0603_OSRAM_LG-Q396-PS-35_GREEN_1A2K_H0P4]  (hidden comment: LED_green)
R28  value 1K  [R0603]  (hidden comment: Resistor)
SB2  value 0R  [SOLDER-BRIDGE_R0603-0R]  (hidden comment: SB_ON)
U5  LD1117S50TR  [REG_SOT223-TAB]
U6  LDL112PV33R  [ICC_DFN6-EPAD_3X3_P095]

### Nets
3V3: JP6.2(NO) SB2.2
5V: C21.2 C22.2 JP5.2 JP5.4 JP5.6 JP5.8 R28.1 U6.1(EN) U6.6(Vin)
5V_USB_CHG: JP5.7
5V_USB_STLK: JP5.1
E5V: JP5.5
GND: C17.1 C18.1 C19.1 C20.1 C21.1 C22.1 LD3.2 U5.1(Gnd) U6.2(GND) U6.EP
VDD: JP6.1(COMMON)
VIN: C18.2 U5.3(Vin)
VIN_5V: C17.2 JP5.3 U5.2(Vout) U5.4(Tab)
NetC19_2: C19.2 C20.2 SB2.1 U6.4(Vout)
NetLD3_1: LD3.1 R28.2

Not connected (* = marked no-connect by the designer): U6 3(NC)* 5(NC)*

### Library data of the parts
C17 C18 = MCD-00014: Capacitor, MLCC, 10uF, 25V, X5R, +/-10%, 0805, T=0.85mm; Manufacturer_Part_Number: CC0805KRX5R8BB106; Manufacturer: YAGEO; Part_Preference: Recommended; Full_Alternate_Internal_Part_Number: MCD-02385; Partial_Alternate_Internal_Part_Number: MCD-03053; Component_Country_Of_Origin: China; ShowFields: YES; ID: 2468
C19 C21 = MCD-00211: as C1 on sheet ST_LINK_V2-1
C20 C22 = MCD-00010: as C6 on sheet ST_LINK_V2-1
HW5 HW8 = MCD-00043: as HW6 on sheet ST_LINK_V2-1
JP5 = MCD-00686: Header, 4x2, 2.54mm, VR, TH, T=5.84mm/2.54mm; Part_Type: Connector; Manufacturer_Part_Number: TSW-104-07-G-D; Manufacturer: SAMTEC; Part_Preference: Recommended; Partial_Alternate_Internal_Part_Number: MCD-01661, MCD-03721; Order_Code_RS: 161-2260; Component_Country_Of_Origin: China, Costa Rica, Malaysia, USA, Vietnam; ShowFields: YES; ID: 3062
JP6 = MCD-00683: Header, 2x1, 2.54mm, VR, TH, T=5.84mm/2.54mm; Part_Type: Connector; Manufacturer_Part_Number: TSW-102-07-G-S; Manufacturer: SAMTEC; Part_Preference: Recommended; Full_Alternate_Internal_Part_Number: MCD-02389; Partial_Alternate_Internal_Part_Number: MCD-02957, MCD-03720; Order_Code_RS: 155-5312; Component_Country_Of_Origin: China, Costa Rica, Malaysia, USA, Vietnam; ShowFields: YES; ID: 3057
LD3 = MCD-00588: LED, Green, 2V, 20mA, 0603; Part_Type: Display; Manufacturer_Part_Number: LG Q396-PS-35; Manufacturer: OSRAM OPTO SEMICONDUCTORS; Part_Preference: Recommended; Partial_Alternate_Internal_Part_Number: MCD-02400, MCD-03155, MCD-02901; Component_Country_Of_Origin: Unknown; ShowFields: YES; ID: 3155
R28 = MCD-00070: as R16 on sheet ST_LINK_V2-1
SB2 = MCD-00071: as SB11 on sheet ST_LINK_V2-1
U5 = MCD-00088: LDO, Adjustable and fixed low drop positive voltage regulator; Part_Type: IC; Manufacturer: STMICROELECTRONICS; BMS_Part_Number: 9176133; Part_Preference: Recommended; Manufacturer_HQ_COO: EU; Order_Code_RS: 165-7748; Component_Country_Of_Origin: China; ShowFields: YES; ID: 2503
U6 = MCD-00664: LDO,  1.2A, Switch, Low quiescent current LDO with reverse current protection; Part_Type: IC; Manufacturer: STMICROELECTRONICS; BMS_Part_Number: 9176253; Part_Preference: Recommended; Manufacturer_HQ_COO: EU; Component_Country_Of_Origin: China; ShowFields: YES; ID: 3075

## Sheet HW_Mechanical_Parts.SchDoc: HW Mechanical parts
size A4; SheetNumber: 7; SheetTotal: 7
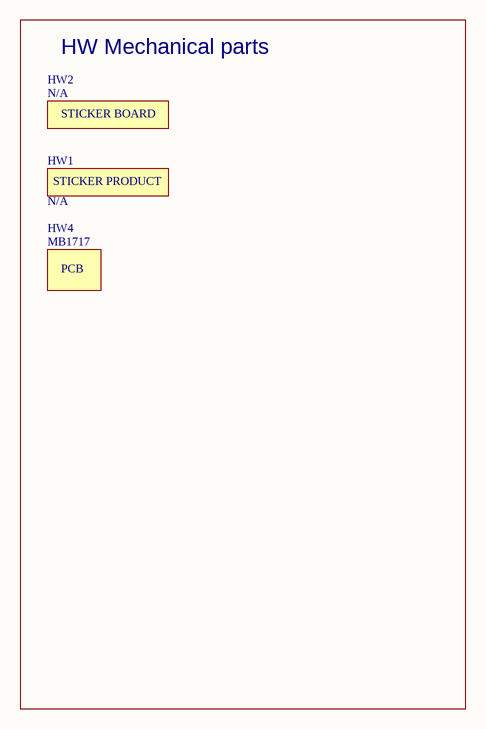
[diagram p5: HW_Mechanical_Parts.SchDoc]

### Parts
HW1  STICKER_PRODUCT  [STICKER_PRODUCT_25X9]  (value not drawn)  (no BOM)
HW2  STICKER_BOARD  [STICKER_BOARD_25X9]  (value not drawn)  (no BOM)
HW4  value MB1717  (hidden comment: PCB)  (mechanical)

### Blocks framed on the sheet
HW Mechanical parts: HW1 HW2 HW4

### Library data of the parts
HW1 = MCD-00547: Sticker product, 25x9mm; Part_Type: Misc; Part_Preference: Recommended; ShowFields: YES; ID: 3197; Component_Country_Of_Origin: Unknown
HW2 = MCD-00235: Sticker Board, 25x9mm; Part_Type: Misc; Part_Preference: Recommended; ShowFields: YES; ID: 2632; Component_Country_Of_Origin: Unknown
HW4 = MCD-02488: MB1717 PCB; Part_Preference: Recommended; Component_Country_Of_Origin: Unknown; ShowFields: YES; ID: 4594

## Sheet Arduino_Morpho_connectors.SchDoc: Connectors
size A4; CompanyName: STMicroelectronics; Organization: Microcontrollers Division; SheetNumber: 4; SheetTotal: 7
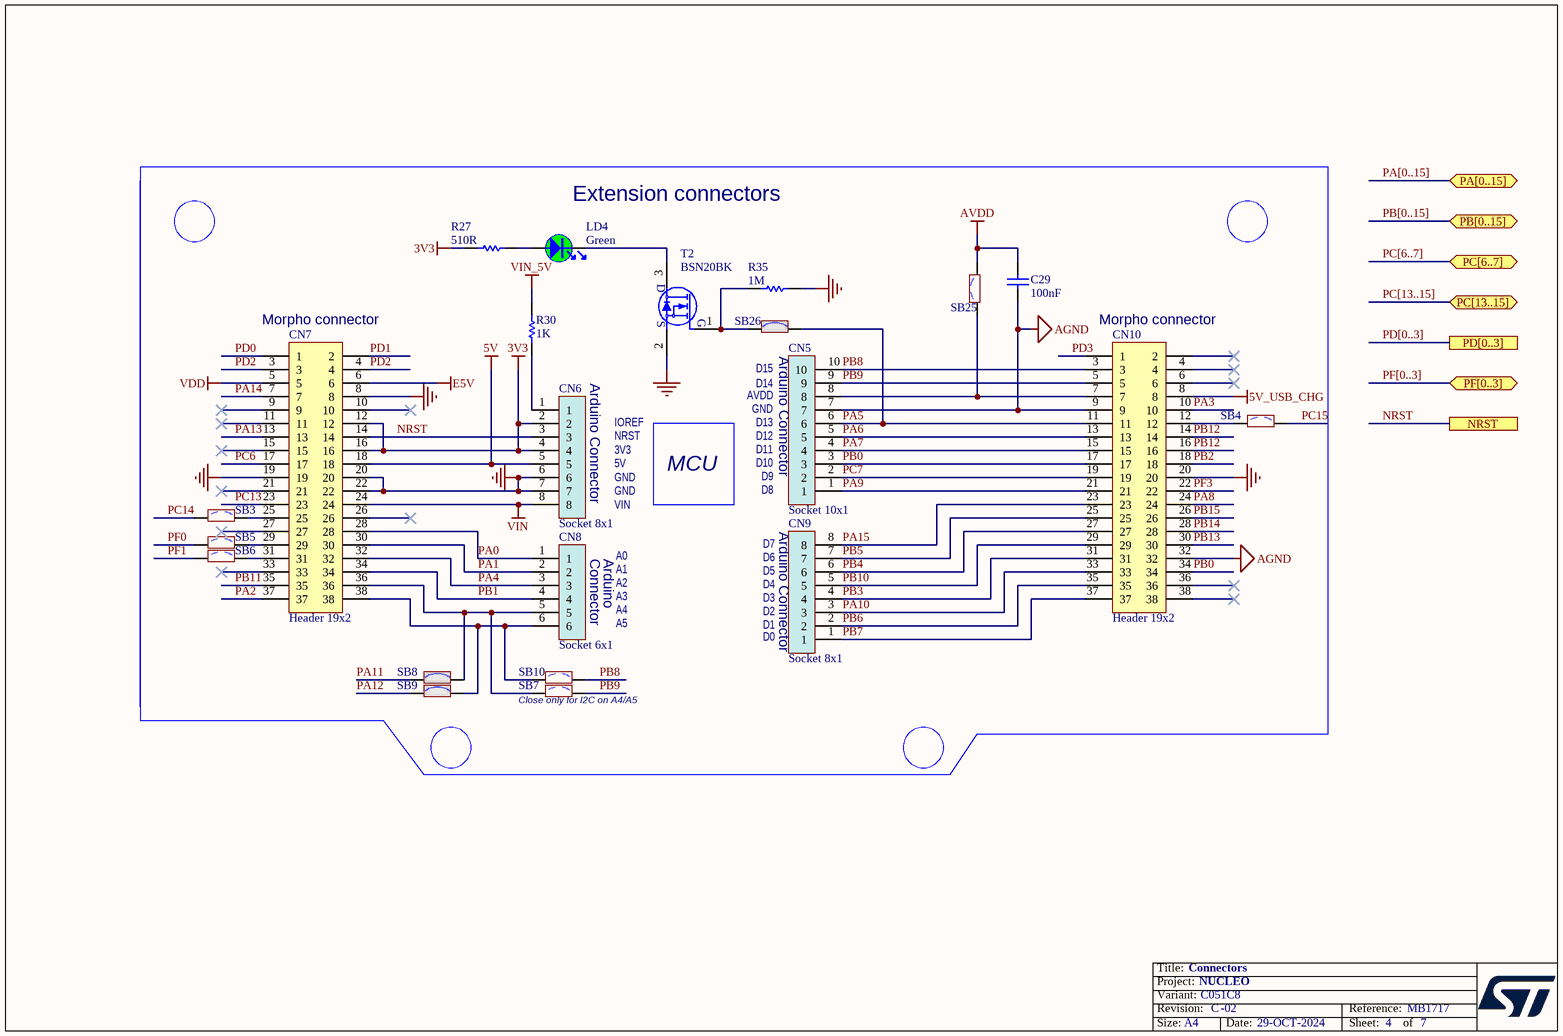
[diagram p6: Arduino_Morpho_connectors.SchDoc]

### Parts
C29  value 100nF  [C0603]  (hidden comment: Capacitor)
CN5  Socket 10x1  [CON_SAMTEC_SSW-110-01-X-S]
CN6  Socket 8x1  [CON_SAMTEC_SSW-108-01-X-S]
CN7  Header 19x2  [CON_SAMTEC_TSW-119-09-X-D]
CN8  Socket 6x1  [CON_SAMTEC_SSW-106-01-X-S]
CN9  Socket 8x1  [CON_SAMTEC_SSW-108-01-X-S]
CN10  Header 19x2  [CON_SAMTEC_TSW-119-09-X-D]
LD4  value Green  [LED_0603_OSRAM_LG-Q396-PS-35_GREEN_1A2K_H0P4]  (hidden comment: LED_green)
R27  value 510R  [R0603]  (hidden comment: Resistor)
R30  value 1K  [R0603]  (hidden comment: Resistor)
R35  value 1M  [R0603]  (hidden comment: Resistor)
SB3  SB_OFF  [SOLDER-BRIDGE_R0603-0R]  (value not drawn)
SB4  SB_OFF  [SOLDER-BRIDGE_R0603-0R]  (value not drawn)
SB5  SB_OFF  [SOLDER-BRIDGE_R0603-0R]  (value not drawn)
SB6  SB_OFF  [SOLDER-BRIDGE_R0603-0R]  (value not drawn)
SB7  SB_OFF  [SOLDER-BRIDGE_R0603-0R]  (value not drawn)
SB8  SB_ON  [SOLDER-BRIDGE_R0603-0R]  (value not drawn)
SB9  SB_ON  [SOLDER-BRIDGE_R0603-0R]  (value not drawn)
SB10  SB_OFF  [SOLDER-BRIDGE_R0603-0R]  (value not drawn)
SB25  SB_OFF  [SOLDER-BRIDGE_R0603-0R]  (value not drawn)
SB26  SB_ON  [SOLDER-BRIDGE_R0603-0R]  (value not drawn)
T2  value BSN20BK  [MOS_SOT23]  (hidden comment: BSN20)

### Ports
NRST, PA[0..15] (bidir), PB[0..15] (bidir), PC[6..7] (bidir), PC[13..15] (bidir), PD[0..3], PF[0..3] (bidir)

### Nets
3V3: CN6.2 CN6.4 CN7.12 CN7.16 R27.2
5V: CN6.5 CN7.18
5V_USB_CHG: CN10.8
AGND: C29.1 CN5.7 CN10.9 CN10.32
AVDD: C29.2 SB25.2
E5V: CN7.6
GND: CN6.6 CN6.7 CN7.8 CN7.19 CN7.20 CN7.22 CN10.20 R35.2 T2.2(S)
VDD: CN7.5
VIN: CN6.8 CN7.24
VIN_5V: R30.1
NRST: CN6.3 CN7.14 ; port NRST
PA0: CN7.28 CN8.1
PA1: CN7.30 CN8.2
PA2: CN7.37
PA3: CN10.10
PA4: CN7.32 CN8.3
PA5: CN5.6 CN10.11 SB26.2
PA6: CN5.5 CN10.13
PA7: CN5.4 CN10.15
PA8: CN10.24
PA9: CN5.1 CN10.21
PA10: CN9.3 CN10.33
PA11: SB8.1
PA12: SB9.1
PA13: CN7.13
PA14: CN7.7
PA15: CN9.8 CN10.23
PB0: CN5.3 CN10.17 CN10.34
PB1: CN7.34 CN8.4
PB2: CN10.18
PB3: CN9.4 CN10.31
PB4: CN9.6 CN10.27
PB5: CN9.7 CN10.25
PB6: CN9.2 CN10.35
PB7: CN9.1 CN10.37
PB8: CN5.10 CN10.3 SB10.2
PB9: CN5.9 CN10.5 SB7.2
PB10: CN9.5 CN10.29
PB11: CN7.35
PB12: CN10.14 CN10.16
PB13: CN10.30
PB14: CN10.28
PB15: CN10.26
PC6: CN7.17
PC7: CN5.2 CN10.19
PC13: CN7.23
PC14: SB3.1
PC15: SB4.2
PD0: CN7.1
PD1: CN7.2
PD2: CN7.3 CN7.4
PD3: CN10.1
PF0: SB5.1
PF1: SB6.1
PF3: CN10.22
NetCN5_8: CN5.8 CN10.7 SB25.1
NetCN6_1: CN6.1 R30.2
NetCN7_25: CN7.25 SB3.2
NetCN7_29: CN7.29 SB5.2
NetCN7_31: CN7.31 SB6.2
NetCN7_36: CN7.36 CN8.5 SB7.1 SB8.2
NetCN7_38: CN7.38 CN8.6 SB9.2 SB10.1
NetCN10_12: CN10.12 SB4.1
NetLD4_1: LD4.1 R27.1
NetLD4_2: LD4.2 T2.3(D)
NetR35_1: R35.1 SB26.1 T2.1(G)

Not connected (* = marked no-connect by the designer): CN7 9* 10* 11* 15* 21* 26* 27* 33*; CN10 2* 4* 6* 36* 38*

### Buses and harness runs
bus PA[0..15] = port PA[0..15]
bus PB[0..15] = port PB[0..15]
bus PC[6..7] = port PC[6..7]
bus PC[13..15] = port PC[13..15]
bus PD[0..3] = port PD[0..3]
bus PF[0..3] = port PF[0..3]

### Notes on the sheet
- (near LD4) Extension connectors
- (near CN7) Morpho connector
- (near CN6) Arduino Connector
- D15
- Arduino Connector
- (near CN10) Morpho connector
- NRST
- IOREF
- AVDD
- (near CN5) GND
- (near CN5) D12
- (near CN5) D13
- D14
- GND
- VIN
- 5V
- 3V3
- MCU
- (near CN5) D10
- (near CN5) D11
- (near CN5) D9
- D8
- (near CN8) Connector
- (near CN8) Arduino
- A0
- A1
- A2
- (near CN9) D5
- (near CN9) D6
- D7
- (near CN9) Arduino Connector
- A5
- A3
- A4
- (near CN9) D0
- (near CN9) D1
- (near CN9) D2
- (near CN9) D3
- (near CN9) D4
- (near SB7) Close only for I2C on A4/A5

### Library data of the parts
C29 = MCD-00211: as C1 on sheet ST_LINK_V2-1
CN5 = MCD-02080: Socket, 10x1, 2.54mm, VR, TH, T=8.51/2.64mm; Manufacturer_Part_Number: SSW-110-01-G-S; Manufacturer: SAMTEC; Part_Type: Connector; Part_Preference: Recommended; Partial_Alternate_Internal_Part_Number: MCD-03160; Order_Code_RS: 765-5736; Component_Country_Of_Origin: China, Costa Rica, Malaysia, USA, Vietnam; ShowFields: YES; ID: 4180
CN6 = MCD-01743: Socket, 8x1, 2.54mm, VR, TH, T=8.51/2.64mm; Manufacturer_Part_Number: SSW-108-01-G-S; Manufacturer: SAMTEC; Part_Type: Connector; Part_Preference: Recommended; Partial_Alternate_Internal_Part_Number: MCD-03161; Order_Code_RS: 765-5698; Component_Country_Of_Origin: China, Costa Rica, Malaysia, USA, Vietnam; ShowFields: YES; ID: 3843
CN7 CN10 = MCD-00213: Header, 19x2, 2.54mm, VR, TH, T=5.84mm/10.16mm; Manufacturer_Part_Number: TSW-119-09-G-D; Manufacturer: SAMTEC; Part_Type: Connector; Part_Preference: Recommended; Partial_Alternate_Internal_Part_Number: MCD-03736, MCD-03787; Component_Country_Of_Origin: China, Costa Rica, Malaysia, USA, Vietnam; ShowFields: YES; ID: 2656
CN8 = MCD-02079: Socket, 6x1, 2.54mm, VR, TH, T=8.51/2.64mm; Part_Type: Connector; Manufacturer_Part_Number: SSW-106-01-G-S; Manufacturer: SAMTEC; Part_Preference: Recommended; Partial_Alternate_Internal_Part_Number: MCD-03162, MCD-04189; Order_Code_RS: 765-5666; Component_Country_Of_Origin: China, Costa Rica, Malaysia, USA, Vietnam; ShowFields: YES; ID: 4179
CN9 = MCD-01743: Socket, 8x1, 2.54mm, VR, TH, T=8.51/2.64mm; Part_Type: Connector; Manufacturer_Part_Number: SSW-108-01-G-S; Manufacturer: SAMTEC; Part_Preference: Recommended; Partial_Alternate_Internal_Part_Number: MCD-03161; Order_Code_RS: 765-5698; Component_Country_Of_Origin: China, Costa Rica, Malaysia, USA, Vietnam; ShowFields: YES; ID: 3843
LD4 = MCD-00588: as LD3 on sheet Power
R27 = MCD-00225: Resistor, 510R, 0603, +/-1%, 1/10W; Manufacturer_Part_Number: RC0603FR-07510RL; Manufacturer: YAGEO; Part_Preference: Recommended; Component_Country_Of_Origin: China; ShowFields: YES; ID: 2644
R30 = MCD-00070: as R16 on sheet ST_LINK_V2-1
R35 = MCD-00257: Resistor, 1M, 0603, +/-1%, 1/10W; Manufacturer_Part_Number: RC0603FR-071ML; Manufacturer: YAGEO; Part_Preference: Recommended; Component_Country_Of_Origin: China; ShowFields: YES; ID: 2612
SB3 SB4 SB7 SB10 SB25 = MCD-00072: as SB1 on sheet ST_LINK_V2-1
SB5 SB6 = MCD-00072: Resistor, 0R, SB0603, 5%, 0.1W; Manufacturer_Part_Number: RC0603JR-070RL; Manufacturer: YAGEO; Part_Preference: Recommended; Manufacturer_HQ_COO: Unknown; Component_Country_Of_Origin: China; Order_Code_RS: 199-5647; ShowFields: YES; ID: 2520
SB8 SB9 SB26 = MCD-00071: as SB11 on sheet ST_LINK_V2-1
T2 = MCD-01969: Transistor, MOSFET, N-CH, 60V, 265mA, SOT23-3; Manufacturer: NEXPERIA; Part_Preference: Recommended; Order_Code_RS: 136-4845; Component_Country_Of_Origin: China; ShowFields: YES; ID: 4069

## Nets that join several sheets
3V3: ST_LINK_V2-1 (R23.1), Power (JP6.2 SB2.2), Arduino_Morpho_connectors (5 pins)
5V: ST_LINK_V2-1 (D1.1), Power (9 pins), Arduino_Morpho_connectors (CN6.5 CN7.18)
5V_USB_CHG: ST_LINK_V2-1 (10 pins), Power (JP5.7), Arduino_Morpho_connectors (CN10.8)
5V_USB_STLK: ST_LINK_V2-1 (C14.2 U3.1), Power (JP5.1)
AGND: STM32_microcontroller_IOs (C31.1 SB28.2), Arduino_Morpho_connectors (C29.1 CN5.7 CN10.9 CN10.32)
AVDD: STM32_microcontroller_IOs (C31.2 SB30.1 U7.5), Arduino_Morpho_connectors (C29.2 SB25.2)
E5V: ST_LINK_V2-1 (D4.1), Power (JP5.5), Arduino_Morpho_connectors (CN7.6)
GND: ST_LINK_V2-1 (47 pins), STM32_microcontroller_IOs (18 pins), Power (10 pins), Arduino_Morpho_connectors (9 pins)
VDD: STM32_microcontroller_IOs (5 pins), Power (JP6.1), Arduino_Morpho_connectors (CN7.5)
VIN: Power (C18.2 U5.3), Arduino_Morpho_connectors (CN6.8 CN7.24)
VIN_5V: ST_LINK_V2-1 (D5.1), Power (C17.2 JP5.3 U5.2 U5.4), Arduino_Morpho_connectors (R30.1)
MCO: ST_LINK_V2-1 (SB20.2), STM32_microcontroller_IOs (SB29.2)
NRST: ST_LINK_V2-1 (SB23.2), STM32_microcontroller_IOs (5 pins), Arduino_Morpho_connectors (CN6.3 CN7.14)
PA0: STM32_microcontroller_IOs (U7.11), Arduino_Morpho_connectors (CN7.28 CN8.1)
PA1: STM32_microcontroller_IOs (U7.12), Arduino_Morpho_connectors (CN7.30 CN8.2)
PA2: STM32_microcontroller_IOs (SB27.2 U7.13), Arduino_Morpho_connectors (CN7.37)
PA3: STM32_microcontroller_IOs (SB32.2 U7.14), Arduino_Morpho_connectors (CN10.10)
PA4: STM32_microcontroller_IOs (U7.15), Arduino_Morpho_connectors (CN7.32 CN8.3)
PA5: STM32_microcontroller_IOs (U7.16), Arduino_Morpho_connectors (CN5.6 CN10.11 SB26.2)
PA6: STM32_microcontroller_IOs (U7.17), Arduino_Morpho_connectors (CN5.5 CN10.13)
PA7: STM32_microcontroller_IOs (U7.18), Arduino_Morpho_connectors (CN5.4 CN10.15)
PA8: STM32_microcontroller_IOs (U7.28), Arduino_Morpho_connectors (CN10.24)
PA9: STM32_microcontroller_IOs (U7.29), Arduino_Morpho_connectors (CN5.1 CN10.21)
PA10: STM32_microcontroller_IOs (U7.32), Arduino_Morpho_connectors (CN9.3 CN10.33)
PA11: STM32_microcontroller_IOs (U7.33), Arduino_Morpho_connectors (SB8.1)
PA12: STM32_microcontroller_IOs (U7.34), Arduino_Morpho_connectors (SB9.1)
PA13: ST_LINK_V2-1 (SB17.1), STM32_microcontroller_IOs (U7.35), Arduino_Morpho_connectors (CN7.13)
PA14: ST_LINK_V2-1 (SB13.1), STM32_microcontroller_IOs (U7.36), Arduino_Morpho_connectors (CN7.7)
PA15: STM32_microcontroller_IOs (U7.37), Arduino_Morpho_connectors (CN9.8 CN10.23)
PB0: STM32_microcontroller_IOs (U7.19), Arduino_Morpho_connectors (CN5.3 CN10.17 CN10.34)
PB1: STM32_microcontroller_IOs (U7.20), Arduino_Morpho_connectors (CN7.34 CN8.4)
PB2: STM32_microcontroller_IOs (U7.21), Arduino_Morpho_connectors (CN10.18)
PB3: STM32_microcontroller_IOs (U7.42), Arduino_Morpho_connectors (CN9.4 CN10.31)
PB4: STM32_microcontroller_IOs (U7.43), Arduino_Morpho_connectors (CN9.6 CN10.27)
PB5: STM32_microcontroller_IOs (U7.44), Arduino_Morpho_connectors (CN9.7 CN10.25)
PB6: STM32_microcontroller_IOs (SB31.2 U7.45), Arduino_Morpho_connectors (CN9.2 CN10.35)
PB7: STM32_microcontroller_IOs (SB33.2 U7.46), Arduino_Morpho_connectors (CN9.1 CN10.37)
PB8: STM32_microcontroller_IOs (U7.47), Arduino_Morpho_connectors (CN5.10 CN10.3 SB10.2)
PB9: STM32_microcontroller_IOs (U7.48), Arduino_Morpho_connectors (CN5.9 CN10.5 SB7.2)
PB10: STM32_microcontroller_IOs (U7.22), Arduino_Morpho_connectors (CN9.5 CN10.29)
PB11: STM32_microcontroller_IOs (U7.23), Arduino_Morpho_connectors (CN7.35)
PB12: STM32_microcontroller_IOs (U7.24), Arduino_Morpho_connectors (CN10.14 CN10.16)
PB13: STM32_microcontroller_IOs (U7.25), Arduino_Morpho_connectors (CN10.30)
PB14: STM32_microcontroller_IOs (U7.26), Arduino_Morpho_connectors (CN10.28)
PB15: STM32_microcontroller_IOs (U7.27), Arduino_Morpho_connectors (CN10.26)
PC6: STM32_microcontroller_IOs (U7.30), Arduino_Morpho_connectors (CN7.17)
PC7: STM32_microcontroller_IOs (U7.31), Arduino_Morpho_connectors (CN5.2 CN10.19)
PC13: STM32_microcontroller_IOs (SB24.1 U7.1), Arduino_Morpho_connectors (CN7.23)
PC14: STM32_microcontroller_IOs (R31.2 U7.2), Arduino_Morpho_connectors (SB3.1)
PC15: STM32_microcontroller_IOs (R32.2 U7.3), Arduino_Morpho_connectors (SB4.2)
PD0: STM32_microcontroller_IOs (U7.38), Arduino_Morpho_connectors (CN7.1)
PD1: STM32_microcontroller_IOs (U7.39), Arduino_Morpho_connectors (CN7.2)
PD2: STM32_microcontroller_IOs (U7.40), Arduino_Morpho_connectors (CN7.3 CN7.4)
PD3: STM32_microcontroller_IOs (U7.41), Arduino_Morpho_connectors (CN10.1)
PF0: STM32_microcontroller_IOs (R33.2 SB29.1 U7.8), Arduino_Morpho_connectors (SB5.1)
PF1: STM32_microcontroller_IOs (R34.2 U7.9), Arduino_Morpho_connectors (SB6.1)
PF3: STM32_microcontroller_IOs (U7.4), Arduino_Morpho_connectors (CN10.22)

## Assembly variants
C031C6: not fitted C9 C29 JP4 R2 R3 SB1 SB3 SB4 SB5 SB6 SB7 SB10 SB12 SB14 SB16 SB18 SB20 SB25 SB29 SB31 SB33
C051C8_S: not fitted C9 C29 JP4 R2 R3 SB1 SB3 SB4 SB5 SB6 SB7 SB10 SB12 SB14 SB16 SB18 SB20 SB25 SB29 SB31 SB33
C051C8: not fitted C9 C29 JP4 R2 R3 SB1 SB3 SB4 SB5 SB6 SB7 SB10 SB12 SB14 SB16 SB18 SB20 SB25 SB29 SB31 SB33; alternate parts C25 -> MCD-03185, C26 -> MCD-03185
